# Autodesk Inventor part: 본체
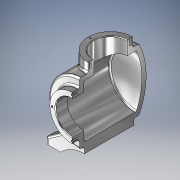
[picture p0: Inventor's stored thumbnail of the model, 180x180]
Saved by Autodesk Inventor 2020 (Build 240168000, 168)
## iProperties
Created: 2023-12
Part Number: 본체
Material: 알루미늄 6061
Document SubType Name: Modeling
Designer: 1강의실14
Density: 2.7 g/cm^3
Appearance: 알루미늄 - 평지
Mass: 1296.71 g
Surface Area: 1060.44 cm^2
Volume: 480.264 cm^3
Author: 1강의실14
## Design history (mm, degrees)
sketch "스케치1"
  geometry: L1 (0, 0)-(0, 108); L2 (0, 108)-(50, 108); L3 (50, 108)-(50, 0); L4 (0, 108)-(0, 0); L5 (50, 108)-(50, 11.664); A1 r 113 centre (0, 113) between (0, 0) and (50, 11.664)
  constraints: 10 end point, 2 collinear, 2 point on circle, 2 point on line, 2 vertical, 2 vertical alignment, 1 centre point, 1 horizontal, 1 horizontal alignment
  dimensions: "d0" = 100 diameter of L2.end L1; "d1" = 108 distance of L2.end L3.end; "d2" = 113 radius of A1; "d3" = 108 distance of L1.start L1.end
revolve "회전1" sketch "스케치1" stored, may be unused: angle "d4" = 90 deg
feature "쉘1" dims "d5" = 7
sketch "스케치2"
  geometry: C1 r 36 at (0, 0); 1 further point
  constraints: 1 centre point, 1 coincident
  dimensions: "d6" = 72 diameter of C1
extrude "돌출1" join sketch "스케치2" distance "d7" = 12; taper "d8" = 0 deg
sketch "스케치3"
  geometry: C1 r 36 at (0, 0) reference; 2 further points
  constraints: 1 coincident
hole "구멍1" sketch "스케치3" at (0, 0) diameter "d9" = 54; stored, may be unused: countersink angle "d13" = 90 deg, drill point angle "d15" = 0 deg; dims "d10" = 6, "d11" = 50, "d12" = 15, "d14" = 19
node "작업 평면2"
  node "작업 평면1"
sketch "스케치4"
  geometry: L1 (0, 0)-(0, -77); L2 (0, -77)-(62, -77); L3 (62, -77)-(62, -67); L4 (62, -67)-(26.694, -42.278); L5 (0, -77)-(0, -50); L6 (0, -77)-(38.5, -77); L7 (0, -77)-(0, -60); L8 (0, -60)-(0, -50); L9 (38.5, -77)-(62, -77); L10 (-62, -67)-(-26.694, -42.278); L11 (0, -77)-(-62, -77); L12 (-62, -77)-(-62, -67); L13 (-38.5, -77)-(-62, -77); A1 r 50 centre (0, 0) between (26.694, -42.278) and (0, -50) reference; A2 r 52.096 centre (0, -112.096) between (38.5, -77) and (0, -60); A3 r 52.096 centre (0, -112.096) between (0, -60) and (-38.5, -77); 1 further point
  constraints: 26 end point, 6 point on circle, 5 point on line, 4 symmetric about line, 2 centre point, 2 collinear, 2 vertical, 1 perpendicular, 1 other
  dimensions: "d18" = 77 distance of L1.start L1.end; "d19" = 62 distance of L1.end L2.end; "d20" = 10 distance of L2.end L3.end; "d21" = 55 deg angle of L3 L4; "d22" = 38.5 distance of L1.end L6.end; "d23" = 17 distance of L1.end L7.end
extrude "돌출2" join sketch "스케치4" distance "d24" = 80; taper "d25" = 0 deg
node "작업 평면4"
sketch "스케치6" dims "d47" = 10
  geometry: L1 (-62, 100)-(-62, 20) reference; L2 (-62, 20)-(-62, 40); L3 (-62, 40)-(-54, 40); L4 (-54, 47)-(-62, 47); L5 (-54, 33)-(-62, 33); L6 (-62, 80)-(-54, 80); L7 (-54, 87)-(-62, 87); L8 (-54, 73)-(-62, 73); L9 (0, -24)-(0, 144) reference; L10 (54, 73)-(62, 73); L11 (62, 80)-(54, 80); L12 (54, 87)-(62, 87); L13 (54, 47)-(62, 47); L14 (62, 40)-(54, 40); L15 (54, 33)-(62, 33); L16 (-62, 87)-(-62, 73); L17 (-62, 47)-(-62, 33); L18 (62, 87)-(62, 73); L19 (62, 100)-(62, 20) reference; L20 (62, 47)-(62, 33); A1 r 7 centre (-54, 40) between (-54, 33) and (-54, 47); A2 r 7 centre (-54, 80) between (-54, 73) and (-54, 87); A3 r 7 centre (54, 80) between (54, 87) and (54, 73); A4 r 7 centre (54, 40) between (54, 47) and (54, 33); 1 further point
  constraints: 34 end point, 14 symmetric about line, 8 point on circle, 4 centre point, 4 coincident, 4 collinear, 3 point on line, 2 perpendicular, 2 tangent, 1 horizontal, 1 vertical, 13 other
  dimensions: "d39" = 20 distance of L1.end L2.end; "d40" = 8 horizontal distance of L1.end L3.end; "d41" = 14 diameter of A1; "d44" = 40 distance of L3.end L6.end
extrude "돌출3" cut sketch "스케치6" stored distance "d49" = 80; taper "d50" = 0 deg
sketch "스케치7"
  geometry: A1 r 7 centre (54, -80) between (54, -73) and (54, -87) reference; A2 r 7 centre (54, -40) between (54, -33) and (54, -47) reference; A3 r 7 centre (-54, -80) between (-54, -87) and (-54, -73) reference; A4 r 7 centre (-54, -40) between (-54, -47) and (-54, -33) reference; 5 further points
  constraints: 4 coincident
hole "구멍2" sketch "스케치7" at (54, -80), (54, -40), (-54, -80), (-54, -40) diameter "d51" = 9; stored, may be unused: countersink angle "d55" = 90 deg, drill point angle "d57" = 0 deg; dims "d52" = 6, "d53" = 50, "d54" = 15, "d56" = 19
node "작업 평면5"
sketch "스케치8"
  geometry: L1 (-27, 120)-(27, 120) reference; L2 (0, 120)-(0, 58); C1 r 36 at (0, 58); 1 further point
  constraints: 2 end point, 1 centre point, 1 coincident, 1 midpoint, 1 vertical
  dimensions: "d59" = 62 distance of L2.start L2.end; "d60" = 72 diameter of C1
extrude "돌출4" join sketch "스케치8" stored distance "d61" = 80; taper "d62" = 0 deg
sketch "스케치10"
  geometry: C1 r 36 at (0, 0) reference; 2 further points
  constraints: 1 coincident
hole "구멍3" sketch "스케치10" at (0, 0) diameter "d65" = 54; stored, may be unused: countersink angle "d69" = 90 deg, drill point angle "d71" = 0 deg; dims "d66" = 6, "d67" = 50, "d68" = 15, "d70" = 67.7454
fillet "모깎기1" dims "d72" = 3
fillet "모깎기2" dims "d73" = 3
chamfer "모따기1" distance "d74" = 1; stored, may be unused: second distance "d75" = 2, angle "d76" = 45 deg
chamfer "모따기2" distance "d77" = 1; stored, may be unused: second distance "d78" = 2, angle "d79" = 45 deg
fillet "모깎기3" dims "d80" = 3
fillet "모깎기4" dims "d81" = 3
fillet "모깎기5" dims "d82" = 3
sketch "스케치11" dims "d83" = 65
  geometry: L1 (0, 0)-(0, 32.5); 1 further point
  constraints: 2 end point, 1 coincident, 1 vertical, 1 vertical alignment, 2 other
hole "구멍4" sketch "스케치11" at (0, 32.5) diameter "d84" = 3.242; stored, may be unused: countersink angle "d88" = 90 deg, drill point angle "d90" = 118 deg; dims "d85" = 8, "d86" = 50, "d87" = 15, "d89" = 10
sketch "스케치12" dims "d94" = 65
  geometry: L1 (0, 0)-(0, 32.5); C1 r 36 at (0, 0) reference; 2 further points
  constraints: 2 end point, 1 vertical, 1 vertical alignment, 3 other
hole "구멍5" sketch "스케치12" at (0, 32.5) diameter "d95" = 3.242; stored, may be unused: countersink angle "d99" = 90 deg, drill point angle "d101" = 118 deg; dims "d96" = 8, "d97" = 50, "d98" = 15, "d100" = 10
node "작업 평면6"
sketch "스케치13"
  geometry: L1 (36, 120)-(-36, 120) reference; L2 (65, 22)-(65, 94) reference; L3 (65, 58)-(-77, 58); L4 (-77, 100)-(-77, 20) reference; 2 further points
  constraints: 2 end point, 1 horizontal, 1 horizontal alignment, 1 midpoint, 1 point on line, 1 vertical alignment, 1 other
  dimensions: "d106" = 62 vertical distance of L1.start L3.start (derived)
feature "엠보싱1" sketch "스케치13" dims "d0" = 100, "d1" = 108, "d2" = 113, "d3" = 108, "d10" = 6, "d107" = 0.5, "d108" = 0
feature "분할2"
node "솔리드1"
pattern_circular "원형 패턴1" dims angle "d92" = 360 deg
pattern_circular "원형 패턴2" dims angle "d103" = 360 deg
feature "A9D066F2-1C7D-4E18-AEED-F7BC21143FA4" dims "d9" = 54, "d10" = 6, "d11" = 50, "d12" = 15, "d13" = 90 deg, "d14" = 19, "d15" = 0
other parameters: "d38" = -71, "d58" = 65
